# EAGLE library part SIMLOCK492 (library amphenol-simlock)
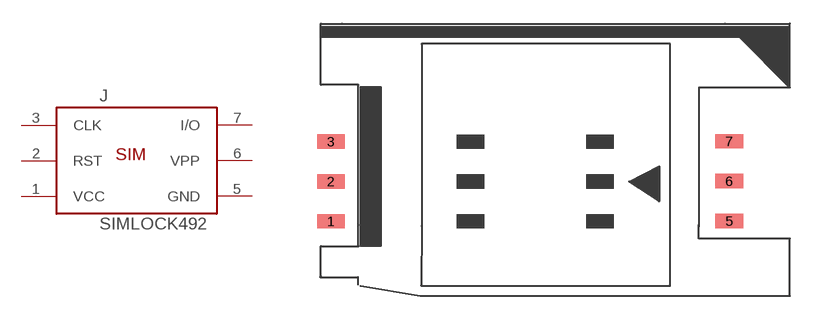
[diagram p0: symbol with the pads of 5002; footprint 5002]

Designator prefix J

## SIMLOCK492  [5002]
1  VCC
2  RST
3  CLK
5  GND
6  VPP
7  I/O

## Footprint 5002 (pad centres in mm)
6 Contacts (3+3), low profile drawn by DeSIG desig@radikaldesig.com
smd 1.778 x 0.914: 1 0.65,0.32; 2 0.65,2.86; 3 0.65,5.4; 5 26.045,0.34; 6 26.045,2.88; 7 26.045,5.42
